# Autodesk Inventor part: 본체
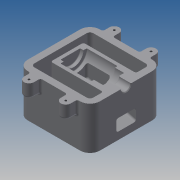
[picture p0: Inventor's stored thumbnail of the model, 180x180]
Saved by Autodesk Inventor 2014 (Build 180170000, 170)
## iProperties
Created: 2018-01
Part Number: 본체
Material: Generic
Document SubType Name: Modeling
Designer: kb542
Density: 1 g/cm^3
Appearance: Default
Author: kb542
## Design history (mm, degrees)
sketch "스케치1"
  geometry: L1 (-55, -55)-(55, -55); L2 (55, -55)-(55, 55); L3 (55, 55)-(-55, 55); L4 (-55, 55)-(-55, -55); L5 (-55, -55)-(55, 55); L6 (55, -55)-(-55, 55); 1 further point
  constraints: 12 end point, 2 midpoint, 2 parallel, 1 horizontal, 1 perpendicular
  dimensions: "d0" = 110 distance of L2.end L3.end; "d1" = 110 distance of L1.end L2.end
extrude "돌출1" new body sketch "스케치1" stored distance "d2" = 65; taper "d3" = 0 deg
sketch "스케치2"
  geometry: L1 (55, -55)-(55, 55) reference; L2 (55, 55)-(-55, 55) reference; L3 (-45, -45)-(45, -45); L4 (45, -45)-(45, 45); L5 (45, 45)-(-45, 45); L6 (-45, 45)-(-45, -45); L7 (-45, -45)-(45, 45); L8 (45, -45)-(-45, 45); 1 further point
  constraints: 12 end point, 2 midpoint, 2 parallel, 1 horizontal, 1 perpendicular
  dimensions: "d4" = 10 distance between parallel lines of L5 L2; "d5" = 10 distance between parallel lines of L1 L4
extrude "돌출2" cut sketch "스케치2" stored distance "d6" = 65; taper "d7" = 0 deg
sketch "스케치4"
  geometry: L1 (-45, 32.5)-(-45, -32.5) reference; L2 (-45, 32.5)-(45, 32.5) reference; L3 (55, 32.5)-(55, -32.5) reference; L4 (35, 32.5)-(35, -2.5); L5 (35, -2.5)-(-45, -23.936); L6 (35, 32.5)-(-45, 32.5); L7 (-45, -23.936)-(-45, 32.5); 1 further point
  constraints: 8 end point, 2 point on line, 1 collinear, 1 parallel, 1 perpendicular
  dimensions: "d11" = 20 distance between parallel lines of L3 L4; "d12" = 30 vertical distance of L3.end L4.end; "d13" = 105 deg angle of L1 L5
extrude "돌출3" join sketch "스케치4" stored distance "d14" = 50; taper "d15" = 0 deg
sketch "스케치5"
  geometry: L1 (-55, -32.5)-(-55, 32.5) reference; L2 (55, 32.5)-(-55, 32.5) reference; L3 (-55, 25)-(-36, 25); L4 (-36, 25)-(-36, 16.5); L5 (-36, 16.5)-(-22, 16.5); L6 (-22, 16.5)-(-22, 12.5); L7 (-22, 12.5)-(25, 12.5); L8 (25, 12.5)-(25, 17.5); L9 (30, 32.5)-(-55, 32.5); L10 (-55, 32.5)-(-55, 25); L11 (25, 17.5)-(30, 17.5); L12 (30, 17.5)-(30, 32.5); 1 further point
  constraints: 20 end point, 5 perpendicular, 3 parallel, 2 collinear, 1 point on line
  dimensions: "d16" = 20 distance between parallel lines of L7 L2; "d17" = 16 distance between parallel lines of L5 L2; "d18" = 7.5 distance between parallel lines of L2 L3; "d20" = 19 distance of L3.start L3.end; "d21" = 14 distance of L4.end L5.end; "d22" = 47 distance of L6.end L7.end; "d23" = 5 distance of L8.end L11.end; "d24" = 15 distance between parallel lines of L2 L11
revolve "회전1" sketch "스케치5" stored, may be unused: angle "d25" = 90 deg
sketch "스케치8"
  geometry: L1 (-55, -3.439)-(-55, -21.439); L2 (-55, -3.439)-(-17, 6.743); L3 (35, -2.5)-(-45, -23.936) reference; L4 (20, -1.343)-(-55, -21.439); L5 (-55, -32.5)-(-55, 32.5) reference; L6 (20, -1.343)-(20, 32.5); L7 (-17, 6.743)-(-17, 32.5); L8 (-22, 12.5)-(25, 12.5) reference; L9 (-17, 32.5)-(20, 32.5); L10 (-36, 32.5)-(-22, 32.5) reference; 3 further points
  constraints: 12 end point, 3 parallel, 2 midpoint, 1 collinear, 1 point on line, 1 vertical, 1 vertical alignment
  dimensions: "d34" = 75 deg angle of L2 L1; "d35" = 18 distance of L1.start L1.end; "d36" = 5 distance between parallel lines of L3 L4; "d38" = 37 distance between parallel lines of L6 L7
extrude "돌출4" cut sketch "스케치8" stored distance "d39" = 30; taper "d40" = 0 deg
fillet "모깎기1" dims "d41" = 15, "d42" = 5
sketch "스케치9"
  geometry: L1 (40, 55)-(-40, 55) reference; L2 (-55, 40)-(-55, -40) reference; L3 (-28, 45)-(-28, 65); L4 (-35.5, 55)-(-35.5, 65); L5 (-20.5, 65)-(-20.5, 55); L6 (-35.5, 55)-(-20.5, 55); A1 r 7.5 centre (-28, 65) between (-20.5, 65) and (-35.5, 65); 3 further points
  constraints: 10 end point, 2 midpoint, 2 point on circle, 2 tangent, 1 centre point, 1 coincident, 1 collinear, 1 parallel, 1 perpendicular, 1 vertical alignment
  dimensions: "d43" = 27 distance from line of L3.end L2; "d44" = 10 distance from line of L3.end L1; "d45" = 7.5 radius of A1
extrude "돌출5" join sketch "스케치9" distance "d46" = 20; taper "d47" = 0 deg
sketch "스케치10"
  geometry: A1 r 7.5 centre (-28, 65) between (-20.5, 65) and (-35.5, 65) reference; 2 further points
  constraints: 1 coincident
hole "구멍1" sketch "스케치10" at (-28, 65) diameter "d48" = 3.242; stored, may be unused: countersink angle "d52" = 90 deg, drill point angle "d54" = 118 deg; dims "d49" = 9, "d50" = 4, "d51" = 2, "d53" = 11
fillet "모깎기2" dims "d55" = 3
fillet "모깎기3" dims "d56" = 3
sketch "스케치11"
  geometry: L1 (55, -40)-(55, -7.5) reference; L2 (-55, 40)-(-55, -40) reference; L3 (-40, -55)-(40, -55) reference; L4 (-28, -65)-(-28, -45); L5 (-35.5, -65)-(-35.5, -55); L6 (-20.5, -55)-(-20.5, -65); L7 (-35.5, -55)-(-20.5, -55); A1 r 7.5 centre (-28, 65) between (-20.5, 65) and (-35.5, 65) reference; A2 r 7.5 centre (-28, -65) between (-35.5, -65) and (-20.5, -65); 3 further points
  constraints: 10 end point, 2 midpoint, 2 parallel, 2 point on circle, 2 point on line, 2 tangent, 1 centre point, 1 coincident, 1 equal radius, 1 vertical alignment
  dimensions: "d60" = 10 distance from line of L3 L4.start; "d61" = 27 distance from line of L2 L4.start
extrude "돌출6" join sketch "스케치11" distance "d62" = 20; taper "d63" = 0 deg
sketch "스케치12"
  geometry: A1 r 7.5 centre (-28, -65) between (-35.5, -65) and (-20.5, -65) reference; 2 further points
  constraints: 1 coincident
hole "구멍2" sketch "스케치12" at (-28, -65) diameter "d64" = 3.242; stored, may be unused: countersink angle "d68" = 90 deg, drill point angle "d70" = 118 deg; dims "d65" = 9, "d66" = 4, "d67" = 2, "d69" = 11
fillet "모깎기4" dims "d71" = 3
fillet "모깎기5" dims "d72" = 3
fillet "모깎기6" dims "d76" = 3
fillet "모깎기7" dims "d77" = 1, "d78" = 3
fillet "모깎기8" dims "d79" = 3
fillet "모깎기9" dims "d80" = 3
sketch "스케치13"
  geometry: L1 (0, 0)-(80, 0) reference; 2 further points
  constraints: 1 vertical alignment, 1 other
  dimensions: "d81" = 20 distance from line of point (40, -20) L1
feature "엠보싱1" sketch "스케치13" dims "d0" = 110, "d1" = 110, "d82" = 0.5, "d83" = 0
chamfer "모따기1" distance "d84" = 1; stored, may be unused: second distance "d85" = 2, angle "d86" = 45 deg
chamfer "모따기2" distance "d87" = 1; stored, may be unused: second distance "d88" = 2, angle "d89" = 45 deg
node "솔리드1"
pattern_linear "직사각형 패턴1" dims "d59" = 56
pattern_linear "직사각형 패턴2" dims "d75" = 56
